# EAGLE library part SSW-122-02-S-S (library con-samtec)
THROUGH-HOLE .025" SQ POST SOCKET Source: Samtec SSW.pdf
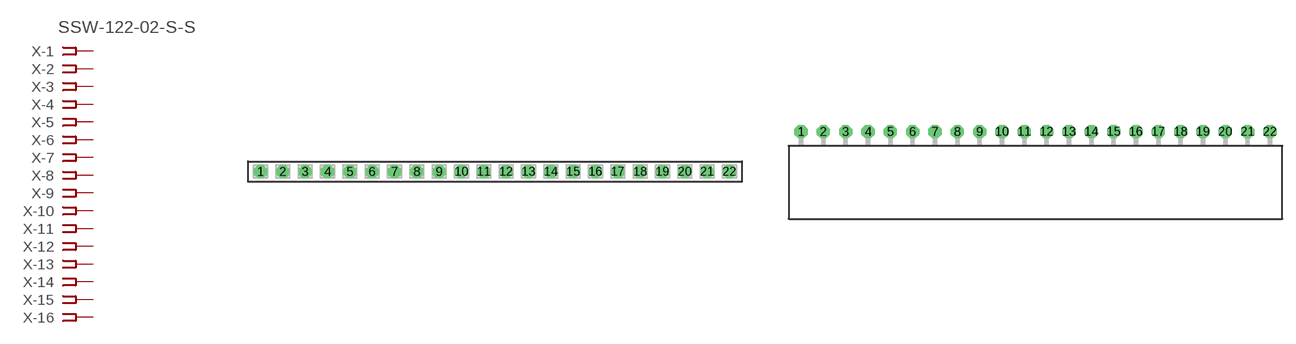
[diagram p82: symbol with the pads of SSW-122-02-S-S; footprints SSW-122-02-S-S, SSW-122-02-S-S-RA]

Designator prefix X; gates -1=FPINV -2=FPIN -3=FPIN -4=FPIN -5=FPIN -6=FPIN -7=FPIN -8=FPIN -9=FPIN -10=FPIN -11=FPIN -12=FPIN -13=FPIN -14=FPIN -15=FPIN -16=FPIN -17=FPIN -18=FPIN -19=FPIN -20=FPIN -21=FPIN -22=FPIN

## SSW-122-02-S-S (MPN: SSW-122-02-S-S; OC_FARNELL: unknown; OC_NEWARK: 11P9675)  [SSW-122-02-S-S]
1  -1:1  pas
2  -2:1  pas
3  -3:1  pas
4  -4:1  pas
5  -5:1  pas
6  -6:1  pas
7  -7:1  pas
8  -8:1  pas
9  -9:1  pas
10  -10:1  pas
11  -11:1  pas
12  -12:1  pas
13  -13:1  pas
14  -14:1  pas
15  -15:1  pas
16  -16:1  pas
17  -17:1  pas
18  -18:1  pas
19  -19:1  pas
20  -20:1  pas
21  -21:1  pas
22  -22:1  pas

## SSW-122-02-S-S-RA (MPN: SSW-122-02-S-S-RA; OC_FARNELL: unknown; OC_NEWARK: 11P9676)  [SSW-122-02-S-S-RA]
Pads as for SSW-122-02-S-S

## Footprint SSW-122-02-S-S (pad centres in mm)
THROUGH-HOLE .025" SQ POST SOCKET Source: Samtec SSW.pdf
drill 1 pad 1.5 octagon: 1 -26.67,0; 2 -24.13,0; 3 -21.59,0; 4 -19.05,0; 5 -16.51,0; 6 -13.97,0; 7 -11.43,0; 8 -8.89,0; 9 -6.35,0; 10 -3.81,0; 11 -1.27,0; 12 1.27,0; 13 3.81,0; 14 6.35,0; 15 8.89,0; 16 11.43,0; 17 13.97,0; 18 16.51,0; 19 19.05,0; 20 21.59,0; 21 24.13,0; 22 26.67,0

## Footprint SSW-122-02-S-S-RA (pad centres in mm)
THROUGH-HOLE .025" SQ POST SOCKET Source: Samtec SSW.pdf
drill 1 pad 1.5 octagon: 1 -26.67,1.524; 2 -24.13,1.524; 3 -21.59,1.524; 4 -19.05,1.524; 5 -16.51,1.524; 6 -13.97,1.524; 7 -11.43,1.524; 8 -8.89,1.524; 9 -6.35,1.524; 10 -3.81,1.524; 11 -1.27,1.524; 12 1.27,1.524; 13 3.81,1.524; 14 6.35,1.524; 15 8.89,1.524; 16 11.43,1.524; 17 13.97,1.524; 18 16.51,1.524; 19 19.05,1.524; 20 21.59,1.524; 21 24.13,1.524; 22 26.67,1.524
